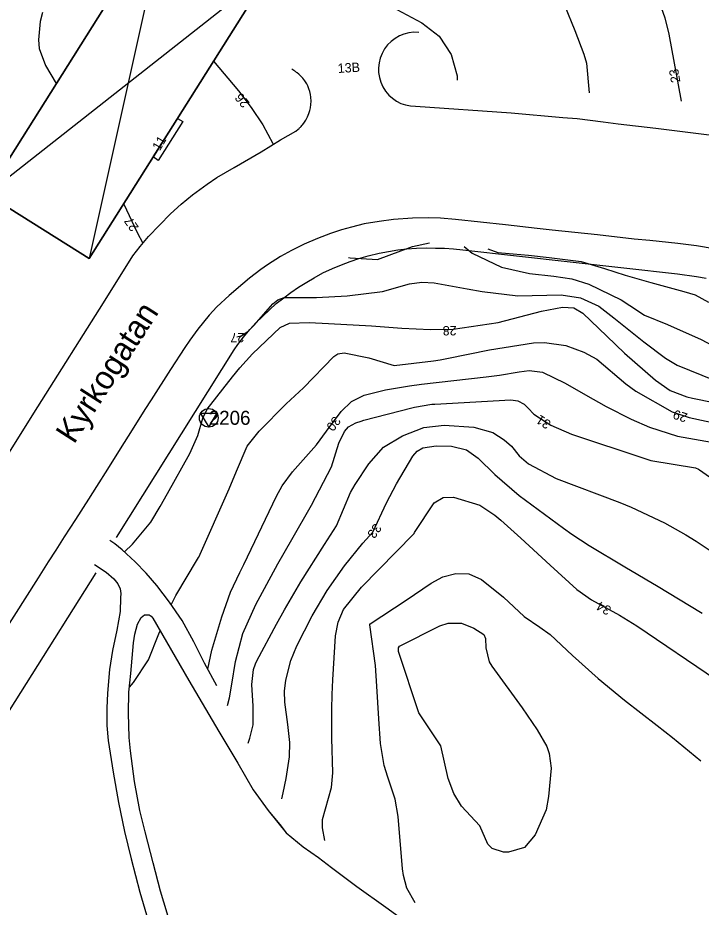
# Model space of a CAD drawing. Extents: x 67169 to 69652, y 20189 to 22818.
# Drawn here: x 69301.4 to 69374.5, y 21050.3 to 21145.5 of the extents above; entities that cross this region are included whole.
import ezdxf

# ---------------------------------------------------------------- set-up
doc = ezdxf.new("R2010")
doc.units = 0
for name, color, linetype in [('BYGGNAD_HUSLIV', 7, 'Continuous'), ('BYGGNAD_HUSLIV 11', 7, 'Continuous'), ('BYGGNADSDETALJER', 7, 'Continuous'), ('BYGGNADSSYMBOLER', 7, 'Continuous'), ('BYGGNADSSYMBOLER 30', 7, 'Continuous'), ('GATUNAMN', 7, 'Continuous'), ('HOJDKURVOR_2014', 7, 'Continuous'), ('HOJDKURVOR_2014 5M', 7, 'Continuous'), ('HOJDKURVOR_TEXTER_2014', 7, 'Continuous'), ('Instruktioner', 7, 'Continuous'), ('MUR_STAKET', 7, 'Continuous'), ('MUR_STAKET_SYMBOL', 7, 'Continuous'), ('Std_Ritningsstämpel', 7, 'Continuous'), ('STOMPUNKTER', 7, 'Continuous'), ('STOMPUNKTER TEXT', 7, 'Continuous'), ('VAGAR 121', 7, 'Continuous'), ('VAGAR 123', 7, 'Continuous')]:
    doc.layers.add(name, color=color, linetype=linetype)

msp = doc.modelspace()

# ---------------------------------------------------------------- linework, layer by layer
at = {"layer": 'BYGGNAD_HUSLIV'}
msp.add_lwpolyline([(69317.366, 21157.37), (69328.375, 21150.486), (69309.014, 21119.709), (69298.005, 21126.594), (69317.366, 21157.37)], dxfattribs=at)
at = {"layer": 'BYGGNAD_HUSLIV 11'}
msp.add_lwpolyline([(69317.366, 21157.37), (69328.375, 21150.486), (69309.014, 21119.709), (69298.005, 21126.594), (69317.366, 21157.37)], dxfattribs=at)
at = {"layer": 'BYGGNADSDETALJER'}
msp.add_lwpolyline([(69319.026, 21134.375), (69316.397, 21130.221), (69315.845, 21130.585), (69318.456, 21134.719), (69319.027, 21134.375)], dxfattribs=at)
at = {"layer": 'BYGGNADSSYMBOLER'}
for p, q in [((69317.366, 21157.37), (69309.014, 21119.709)), ((69298.005, 21126.594), (69328.375, 21150.486))]:
    msp.add_line(p, q, dxfattribs=at)
at = {"layer": 'BYGGNADSSYMBOLER 30'}
for p, q in [((69317.366, 21157.37), (69309.014, 21119.709)), ((69298.005, 21126.594), (69328.375, 21150.486))]:
    msp.add_line(p, q, dxfattribs=at)
at = {"layer": 'HOJDKURVOR_2014'}
for points in [[(69351.137, 21176.42), (69352.173, 21175.723), (69353.027, 21174.885), (69354.031, 21173.563), (69354.447, 21172.837), (69357.678, 21166.393), (69357.906, 21166.066), (69360.992, 21162.6), (69363.449, 21159.576), (69365.624, 21156.343), (69366.808, 21154.328), (69368.227, 21151.54), (69369.606, 21148.321), (69370.608, 21145.495), (69371.019, 21143.745), (69372.337, 21136.549)], [(69335.941, 21162.437), (69342.411, 21161.09), (69345.32, 21160.205), (69351.047, 21157.685), (69352.088, 21157.155), (69354, 21155.848), (69355.049, 21154.891), (69356.407, 21153.308), (69357.509, 21151.537), (69359.86, 21146.831), (69360.97, 21144.131), (69361.93, 21141.581), (69362.227, 21140.629), (69362.509, 21137.469)], [(69304.013, 21146.041), (69303.765, 21145.09), (69303.566, 21143.144), (69303.663, 21142.196), (69304.337, 21140.396), (69305.454, 21138.435)], [(69322.316, 21140.854), (69324.974, 21137.663), (69326.343, 21135.875), (69327.588, 21134.012), (69328.647, 21132.037)], [(69312.705, 21125.536), (69314.134, 21122.495), (69314.746, 21121.351)], [(69336.755, 21119.835), (69336.924, 21119.779), (69339.846, 21119.596), (69343.617, 21120.989), (69345.415, 21121.396)], [(69349.115, 21121.016), (69349.971, 21120.279), (69353.129, 21118.806), (69356.133, 21118.117), (69358.743, 21117.827), (69360.649, 21117.553), (69362.463, 21116.958), (69365.946, 21115.309), (69366.862, 21114.672), (69368.433, 21113.64), (69370.877, 21112.66), (69374.489, 21111.063), (69377.786, 21109.284)], [(69324.818, 21111.341), (69325.264, 21111.458), (69325.974, 21111.888), (69326.644, 21112.59), (69328.672, 21114.878), (69329.198, 21115.289), (69329.877, 21115.535), (69333.312, 21115.546), (69336.607, 21115.717), (69340.392, 21116.199), (69343.294, 21117.025), (69344.595, 21117.195), (69345.907, 21117.128), (69349.445, 21116.485), (69351.04, 21116.198), (69354.865, 21115.72), (69359.501, 21115.826), (69361.594, 21115.515), (69363.533, 21114.625), (69365.157, 21113.384), (69368.35, 21110.785), (69370.665, 21109.035), (69371.939, 21108.298), (69375.876, 21106.71)], [(69312.765, 21088.328), (69313.646, 21089.139), (69315.589, 21091.494), (69316.583, 21093.179), (69317.375, 21094.549), (69319.776, 21098.845), (69320.632, 21100.787), (69321.17, 21102.63), (69321.641, 21103.574), (69324.355, 21107.055), (69325.113, 21108.009), (69326.464, 21109.52), (69329.443, 21112.324), (69330.45, 21112.78), (69332.557, 21112.881), (69334.598, 21112.778), (69339.197, 21112.511), (69341.519, 21112.318), (69342.449, 21112.264), (69345.526, 21112.128), (69347.958, 21112.147), (69352.777, 21112.857), (69357.399, 21114.076), (69359.64, 21114.526), (69360.87, 21114.445), (69361.828, 21113.852), (69364.386, 21111.389), (69366.299, 21109.597), (69369.599, 21106.707), (69371.169, 21105.596), (69372.948, 21104.925), (69373.571, 21104.784), (69378.317, 21103.801)], [(69317.781, 21082.654), (69318.268, 21083.632), (69320.606, 21087.543), (69320.707, 21087.727), (69320.716, 21087.746), (69320.725, 21087.765), (69323.999, 21095.077), (69324.771, 21096.942), (69325.925, 21099.644), (69327.209, 21101.231), (69330.089, 21104.151), (69331.945, 21105.887), (69335.176, 21109.241), (69335.594, 21109.516), (69336.272, 21109.607), (69338.913, 21109.069), (69341.641, 21108.271), (69345.864, 21108.752), (69346.568, 21108.875), (69347.27, 21109.008), (69351.826, 21109.93), (69356.554, 21110.694), (69357.73, 21110.743), (69360.021, 21110.417), (69361.934, 21109.701), (69363.342, 21108.952), (69366.448, 21106.302), (69367.491, 21105.503), (69371.387, 21103.294), (69373.214, 21102.704), (69376.347, 21102.025)], [(69323.798, 21071.866), (69324.002, 21072.693), (69324.268, 21074.145), (69324.655, 21076.574), (69325.462, 21079.564), (69326.828, 21082.67), (69329.193, 21087.049), (69330.687, 21089.637), (69332.795, 21093.311), (69334.938, 21097.412), (69335.719, 21099.959), (69336.312, 21101.209), (69336.76, 21101.713), (69337.536, 21102.127), (69338.101, 21102.321), (69338.389, 21102.403), (69343.527, 21103.735), (69343.829, 21103.81), (69345.666, 21104.109), (69345.976, 21104.132), (69354.134, 21104.585), (69354.89, 21104.491), (69355.566, 21104.14), (69355.97, 21103.695), (69356.601, 21103.042), (69358.404, 21101.894), (69360.629, 21100.906), (69368.469, 21098.296), (69369.092, 21098.102), (69373.873, 21097.299), (69374.209, 21097.171), (69374.312, 21097.108), (69379.098, 21093.73)], [(69326.024, 21067.851), (69326.197, 21068.388), (69326.538, 21069.808), (69326.551, 21071.81), (69326.395, 21074.108), (69326.571, 21075.726), (69326.796, 21076.338), (69326.938, 21076.633), (69329.045, 21080.571), (69329.89, 21082.105), (69331.664, 21085.122), (69334.19, 21089.087), (69335.478, 21091.103), (69336.964, 21094.654), (69337.463, 21095.531), (69338.93, 21097.744), (69340.513, 21099.51), (69342.537, 21100.745), (69344.808, 21101.645), (69346.974, 21101.878), (69350.182, 21101.653), (69352.192, 21101.085), (69353.41, 21100.321), (69354.184, 21099.62), (69355.003, 21098.583), (69356.016, 21097.727), (69358.989, 21096.169), (69365.782, 21093.603), (69367.002, 21093.115), (69370.563, 21091.438), (69372.85, 21090.144), (69373.965, 21089.451), (69377.49, 21087.106)], [(69329.635, 21061.865), (69329.768, 21062.525), (69330.077, 21064.059), (69330.445, 21066.373), (69330.474, 21067.922), (69330.262, 21069.827), (69329.946, 21072.219), (69329.887, 21073.411), (69330.03, 21074.596), (69330.576, 21076.698), (69331.225, 21078.253), (69332.85, 21081.455), (69334.482, 21084.176), (69336.321, 21086.809), (69338.282, 21089.233), (69339.364, 21090.431), (69340.833, 21093.568), (69341.905, 21095.611), (69343.631, 21098.564), (69344.09, 21099.1), (69344.705, 21099.446), (69346.142, 21099.681), (69347.762, 21099.619), (69349.369, 21099.229), (69350.616, 21098.363), (69352.417, 21096.606), (69355.012, 21094.34), (69359.762, 21090.853), (69360.667, 21090.208), (69362.52, 21088.981), (69366.34, 21086.703), (69369.896, 21084.621), (69372.073, 21083.279), (69374.614, 21081.754)], [(69334.232, 21057.4), (69333.981, 21058.757), (69333.964, 21059.666), (69334.918, 21063.096), (69335.072, 21064.646), (69334.972, 21068.381), (69334.959, 21071.494), (69335.006, 21073.049), (69335.078, 21074.604), (69335.358, 21079.32), (69335.631, 21080.786), (69336.231, 21082.158), (69338.128, 21084.539), (69343.713, 21090.224), (69343.763, 21090.284), (69343.832, 21090.381), (69345.928, 21093.58), (69346.897, 21094.149), (69347.989, 21094.176), (69350.801, 21093.331), (69352.406, 21092.254), (69353.071, 21091.695), (69355.195, 21089.794), (69358.35, 21086.908), (69361.176, 21084.273), (69362.742, 21083.18), (69365.768, 21081.526), (69367.61, 21080.391), (69376.137, 21074.632)], [(69313.312, 21073.843), (69313.736, 21074.332), (69315.356, 21076.77), (69316.454, 21079.525), (69316.592, 21079.866)], [(69351.233, 21079.48), (69351.425, 21079.029), (69351.435, 21078.044), (69351.811, 21076.532), (69352.081, 21076.076), (69355.33, 21071.63), (69356.957, 21069.252), (69357.974, 21067.482), (69358.244, 21066.739), (69358.428, 21065.159), (69358.138, 21062.142), (69357.891, 21060.683), (69356.735, 21058.019), (69355.586, 21056.666), (69353.882, 21056.17), (69353.341, 21056.174), (69352.113, 21056.568), (69351.676, 21057.016), (69350.809, 21058.992), (69348.863, 21061.102), (69348.022, 21062.455), (69347.422, 21064.045), (69346.618, 21067.555), (69344.262, 21071.094), (69342.117, 21077.65), (69342.095, 21077.751), (69342.119, 21078.053), (69342.219, 21078.227), (69346.524, 21080.382), (69347.425, 21080.684), (69348.85, 21080.67), (69350.18, 21080.158), (69351.233, 21079.48)]]:
    msp.add_lwpolyline(points, dxfattribs=at)
at = {"layer": 'HOJDKURVOR_2014 5M'}
for points in [[(69329.775, 21152.712), (69335.608, 21149.506), (69341.373, 21146.671), (69344.607, 21144.961), (69346.461, 21143.517), (69347.748, 21141.55), (69348.365, 21139.265), (69348.376, 21138.793)], [(69351.669, 21120.76), (69352.748, 21120.363), (69356.031, 21120.059), (69358.222, 21119.837), (69361.644, 21119.4), (69364.156, 21118.635), (69366.377, 21117.928), (69369.09, 21117.134), (69372.629, 21116.172), (69373.848, 21115.82), (69375.29, 21115.029)], [(69321.685, 21075.756), (69322.144, 21077.781), (69323.201, 21081.361), (69324.122, 21084.007), (69325.134, 21086.118), (69325.563, 21086.975), (69329.064, 21094.288), (69329.659, 21095.38), (69330.755, 21096.89), (69333.34, 21099.787), (69334.381, 21101.253), (69335.967, 21103.355), (69337.064, 21104.408), (69338.427, 21105.083), (69340.713, 21105.662), (69343.272, 21106.082), (69344.561, 21106.282), (69351.495, 21107.046), (69352.91, 21107.228), (69355.001, 21107.589), (69356.084, 21107.722), (69357.498, 21107.568), (69359.933, 21106.37), (69362.13, 21105.132), (69364.32, 21103.88), (69367.004, 21102.516), (69368.949, 21101.657), (69371.97, 21100.693), (69376.198, 21099.942)], [(69343.891, 21050.731), (69342.987, 21052.319), (69342.621, 21053.67), (69342.524, 21054.369), (69342.058, 21060), (69341.737, 21061.833), (69340.971, 21064.209), (69340.576, 21065.455), (69340.193, 21067.811), (69339.996, 21070.438), (69339.801, 21073.949), (69339.628, 21076.144), (69339.021, 21080.507), (69339.028, 21080.541), (69339.051, 21080.608), (69339.058, 21080.623), (69342.917, 21083.161), (69345.583, 21084.977), (69346.858, 21085.646), (69348.251, 21086.01), (69349.645, 21085.952)], [(69349.645, 21085.952), (69350.975, 21085.368), (69353.342, 21083.457), (69355.562, 21081.388), (69357.238, 21080.27), (69358.34, 21079.485), (69360.727, 21077.217), (69363.456, 21074.753), (69366.306, 21072.43), (69369.771, 21069.736), (69371.418, 21068.43), (69374.453, 21065.954)]]:
    msp.add_lwpolyline(points, dxfattribs=at)
at = {"layer": 'MUR_STAKET'}
for points in [[(69311.919, 21089.84), (69324.523, 21109.946), (69324.896, 21110.497), (69325.516, 21111.315), (69326.19, 21112.115), (69326.829, 21112.845), (69327.538, 21113.502), (69328.283, 21114.232), (69329.029, 21114.889), (69329.827, 21115.512), (69330.573, 21116.082), (69331.388, 21116.633), (69332.294, 21117.203), (69333.092, 21117.666), (69334.024, 21118.173), (69335.036, 21118.653), (69335.994, 21119.045), (69336.935, 21119.401), (69337.876, 21119.722), (69338.851, 21119.989), (69340.023, 21120.275), (69341.018, 21120.471), (69342.03, 21120.632), (69342.988, 21120.756), (69344.018, 21120.811), (69345.048, 21120.847), (69346.051, 21120.84), (69347.028, 21120.824), (69348.005, 21120.753), (69348.999, 21120.647), (69371.957, 21118.077), (69373.976, 21117.797), (69375.014, 21117.612)], [(69322.791, 21025.803), (69287.954, 21047.641), (69287.357, 21050.544), (69309.748, 21086.071)], [(69315.646, 21081.425), (69315.819, 21081.204), (69319.664, 21074.55), (69322.864, 21069.092), (69324.898, 21065.694), (69326.568, 21062.83), (69328.144, 21060.629), (69330.098, 21058.253), (69331.91, 21056.744), (69333.533, 21055.581), (69334.935, 21054.512), (69337.643, 21052.5), (69340.745, 21050.283)]]:
    msp.add_lwpolyline(points, dxfattribs=at)
at = {"layer": 'MUR_STAKET_SYMBOL'}
for p, q in [((69343.023, 21120.758), (69343.023, 21120.758)), ((69344.545, 21120.83), (69344.545, 21120.83)), ((69346.03, 21120.84), (69346.03, 21120.84)), ((69347.525, 21120.787), (69347.525, 21120.787)), ((69338.37, 21119.848), (69338.37, 21119.848)), ((69340, 21120.26), (69340, 21120.26)), ((69341.536, 21120.542), (69341.536, 21120.542)), ((69349.081, 21120.625), (69349.081, 21120.625)), ((69350.648, 21120.451), (69350.648, 21120.451)), ((69352.081, 21120.291), (69352.081, 21120.291)), ((69353.673, 21120.112), (69353.673, 21120.112)), ((69354.999, 21119.964), (69354.999, 21119.964)), ((69356.642, 21119.78), (69356.642, 21119.78)), ((69335.505, 21118.845), (69335.505, 21118.845)), ((69336.97, 21119.414), (69336.97, 21119.414)), ((69358.092, 21119.618), (69358.092, 21119.618)), ((69359.645, 21119.444), (69359.645, 21119.444)), ((69361.13, 21119.277), (69361.13, 21119.277)), ((69362.596, 21119.113), (69362.596, 21119.113)), ((69364.097, 21118.945), (69364.097, 21118.945)), ((69334.003, 21118.156), (69334.003, 21118.156)), ((69365.618, 21118.775), (69365.618, 21118.775)), ((69367.03, 21118.618), (69367.03, 21118.618)), ((69368.493, 21118.454), (69368.493, 21118.454)), ((69369.944, 21118.292), (69369.944, 21118.292)), ((69371.497, 21118.117), (69371.497, 21118.117)), ((69373.001, 21117.922), (69373.001, 21117.922)), ((69332.683, 21117.423), (69332.683, 21117.423)), ((69331.337, 21116.608), (69331.337, 21116.608)), ((69330.229, 21115.805), (69330.229, 21115.805)), ((69329.025, 21114.873), (69329.025, 21114.873)), ((69327.893, 21113.849), (69327.893, 21113.849)), ((69326.819, 21112.833), (69326.819, 21112.833)), ((69325.787, 21111.64), (69325.787, 21111.64)), ((69324.867, 21110.455), (69324.867, 21110.455)), ((69324.06, 21109.208), (69324.06, 21109.208)), ((69323.265, 21107.94), (69323.265, 21107.94)), ((69322.452, 21106.644), (69322.452, 21106.644)), ((69321.653, 21105.369), (69321.653, 21105.369)), ((69320.866, 21104.113), (69320.866, 21104.113)), ((69320.075, 21102.85), (69320.075, 21102.85)), ((69319.298, 21101.612), (69319.298, 21101.612)), ((69318.48, 21100.308), (69318.48, 21100.308)), ((69317.696, 21099.055), (69317.696, 21099.055)), ((69316.887, 21097.764), (69316.887, 21097.764)), ((69316.11, 21096.526), (69316.11, 21096.526)), ((69315.259, 21095.169), (69315.259, 21095.169)), ((69314.496, 21093.951), (69314.496, 21093.951)), ((69313.707, 21092.692), (69313.707, 21092.692)), ((69312.905, 21091.412), (69312.905, 21091.412)), ((69312.084, 21090.103), (69312.084, 21090.103)), ((69309.549, 21085.755), (69309.549, 21085.755)), ((69308.74, 21084.473), (69308.74, 21084.473)), ((69307.925, 21083.181), (69307.925, 21083.181)), ((69307.146, 21081.944), (69307.146, 21081.944)), ((69306.342, 21080.667), (69306.342, 21080.667)), ((69305.536, 21079.389), (69305.536, 21079.389)), ((69304.73, 21078.112), (69304.73, 21078.112)), ((69303.924, 21076.829), (69303.924, 21076.829)), ((69303.136, 21075.58), (69303.136, 21075.58)), ((69302.352, 21074.337), (69302.352, 21074.337)), ((69301.492, 21072.971), (69301.492, 21072.971))]:
    msp.add_line(p, q, dxfattribs=at)
at = {"layer": 'Std_Ritningsstämpel'}
msp.add_lwpolyline([(69317.366, 21157.37), (69298.005, 21126.594), (69309.014, 21119.709), (69328.375, 21150.486)], close=True, dxfattribs=at)
at = {"layer": 'STOMPUNKTER'}
msp.add_lwpolyline([(69321.799, 21101.664), (69322.677, 21103.144), (69320.924, 21103.143)], close=True, dxfattribs=at)
msp.add_circle((69321.799, 21102.664), 1, dxfattribs=at)
at = {"layer": 'VAGAR 121'}
for points in [[(69331.11, 21133.346), (69331.371, 21133.559), (69331.463, 21133.643), (69331.519, 21133.695), (69331.561, 21133.736), (69331.602, 21133.777), (69331.636, 21133.812), (69331.683, 21133.862), (69331.758, 21133.945), (69331.832, 21134.034), (69331.975, 21134.213), (69332.188, 21134.527), (69332.366, 21134.867), (69332.516, 21135.231), (69332.613, 21135.552), (69332.677, 21135.841), (69332.731, 21136.205), (69332.748, 21136.562), (69332.73, 21136.988), (69332.683, 21137.272), (69332.608, 21137.606), (69332.522, 21137.894), (69332.398, 21138.202), (69332.29, 21138.434), (69332.091, 21138.738), (69331.856, 21139.024), (69331.753, 21139.136), (69331.705, 21139.187), (69331.634, 21139.259), (69331.425, 21139.454), (69331.26, 21139.589), (69331.185, 21139.647), (69331.125, 21139.692), (69331.074, 21139.729), (69331.003, 21139.778), (69330.963, 21139.805), (69330.91, 21139.837), (69330.678, 21139.98)], [(69343.935, 21136.014), (69354.15, 21135.295), (69359.697, 21134.83), (69361.215, 21134.703), (69363.993, 21134.363), (69365.617, 21134.151), (69369.658, 21133.684), (69379.34, 21132.474), (69381.049, 21132.304)], [(69293.273, 21087.54), (69303.504, 21103.829), (69310.541, 21114.974), (69313.678, 21120.003), (69314.458, 21120.993), (69315.333, 21122.08), (69316.532, 21123.299), (69317.693, 21124.5), (69318.834, 21125.528), (69320.052, 21126.519), (69321.612, 21127.683), (69322.678, 21128.407), (69324.524, 21129.456), (69327.417, 21131.153), (69329.492, 21132.412), (69331.11, 21133.346)], [(69340.023, 21123.688), (69338.423, 21123.418), (69337.079, 21123.078), (69336.015, 21122.786), (69334.823, 21122.387), (69333.421, 21121.848), (69332.007, 21121.251), (69330.652, 21120.584), (69329.473, 21119.916), (69328.094, 21119.039), (69327.382, 21118.525), (69326.156, 21117.624), (69325.443, 21117.016), (69323.971, 21115.764), (69322.675, 21114.536), (69321.857, 21113.66), (69320.631, 21112.151), (69319.791, 21110.993), (69319.231, 21110.175), (69317.702, 21107.838), (69315.625, 21104.587), (69314.948, 21103.558), (69313.593, 21101.373), (69312.309, 21099.338), (69310.955, 21097.175), (69309.789, 21095.328), (69308.925, 21093.972), (69307.524, 21091.786), (69306.333, 21089.915), (69305.424, 21088.489), (69304.63, 21087.25), (69303.532, 21085.531), (69299.762, 21079.592)], [(69375.894, 21120.761), (69374, 21121.074), (69372.013, 21121.342), (69369.01, 21121.631), (69367.315, 21121.806), (69363.399, 21122.247), (69358.537, 21122.769), (69356.947, 21122.918), (69353.558, 21123.314), (69348.204, 21123.893), (69346.615, 21124.021), (69345.317, 21124.055), (69343.599, 21124.042), (69341.565, 21123.9), (69340.023, 21123.688)], [(69322.647, 21073.984), (69321.34, 21076.393), (69320.204, 21078.69), (69318.943, 21080.955), (69317.587, 21082.938), (69316.233, 21084.73), (69315.091, 21086.051), (69313.941, 21087.246), (69312.538, 21088.536), (69311.735, 21089.18), (69311.216, 21089.526)]]:
    msp.add_lwpolyline(points, dxfattribs=at)
msp.add_arc((69343.918, 21139.975), 3.961, 84.90432, 270.2402, dxfattribs=at)
at = {"layer": 'VAGAR 123'}
for points in [[(69309.586, 21086.952), (69310.825, 21086.142), (69311.644, 21085.435), (69312.085, 21084.9), (69312.306, 21084.349), (69312.384, 21083.861), (69312.354, 21083.389), (69312.308, 21081.925), (69311.964, 21079.926), (69311.493, 21077.754), (69311.179, 21075.708), (69310.946, 21073.19), (69310.884, 21071.6), (69310.902, 21069.743), (69311.045, 21068.106), (69311.552, 21064.739), (69312.137, 21061.497), (69312.8, 21058.366), (69313.496, 21055.454), (69314.411, 21051.883), (69315.311, 21048.846)], [(69317.814, 21048.108), (69316.647, 21051.995), (69315.841, 21055.031), (69315.004, 21058.336), (69314.435, 21060.634), (69313.851, 21063.749), (69313.407, 21067.022), (69313.296, 21068.439), (69313.214, 21071.051), (69313.26, 21073.286), (69313.447, 21075.285), (69313.759, 21078.575), (69313.9, 21079.503), (69314.166, 21080.574), (69314.56, 21081.298), (69314.936, 21081.566), (69315.409, 21081.566), (69315.646, 21081.425), (69315.819, 21081.204), (69319.664, 21074.55), (69322.864, 21069.092), (69324.898, 21065.694), (69326.568, 21062.83), (69328.144, 21060.629), (69329.39, 21059.119), (69330.098, 21058.253), (69331.91, 21056.744), (69333.533, 21055.581), (69334.935, 21054.512), (69337.643, 21052.5), (69340.745, 21050.283), (69342.572, 21048.946)]]:
    msp.add_lwpolyline(points, dxfattribs=at)

# ---------------------------------------------------------------- texts
at = {"layer": 'GATUNAMN'}
msp.add_text('Kyrkogatan', height=2.5, rotation=57.27383, dxfattribs=at).set_placement((69307.38, 21099.762))
at = {"layer": 'HOJDKURVOR_TEXTER_2014'}
for s, rotation, p in [('23', 100, (69372.277, 21138.622)), ('26', 130, (69326.226, 21136.386)), ('27', 125, (69314.352, 21123.065)), ('28', 180.45873, (69348.315, 21112.49)), ('27', 180.06538, (69325.601, 21111.759)), ('30', 232.97156, (69335.212, 21102.918)), ('31', 147.50501, (69358.509, 21102.23)), ('29', 162.07848, (69373.105, 21103.096)), ('33', 234.5543, (69339.56, 21091.438)), ('34', 151.3372, (69364.961, 21082.355))]:
    msp.add_text(s, height=1, rotation=rotation, dxfattribs=at).set_placement(p)
at = {"layer": 'Instruktioner'}
for s, rotation, p in [('13B', 3.24672, (69335.628, 21139.576)), ('11', 59.69571, (69316.551, 21131.181))]:
    msp.add_text(s, height=1, rotation=rotation, dxfattribs=at).set_placement(p)
at = {"layer": 'STOMPUNKTER TEXT'}
msp.add_text('2206', height=1.5, dxfattribs=at).set_placement((69321.799, 21101.914))

doc.saveas('drawing.dxf')
